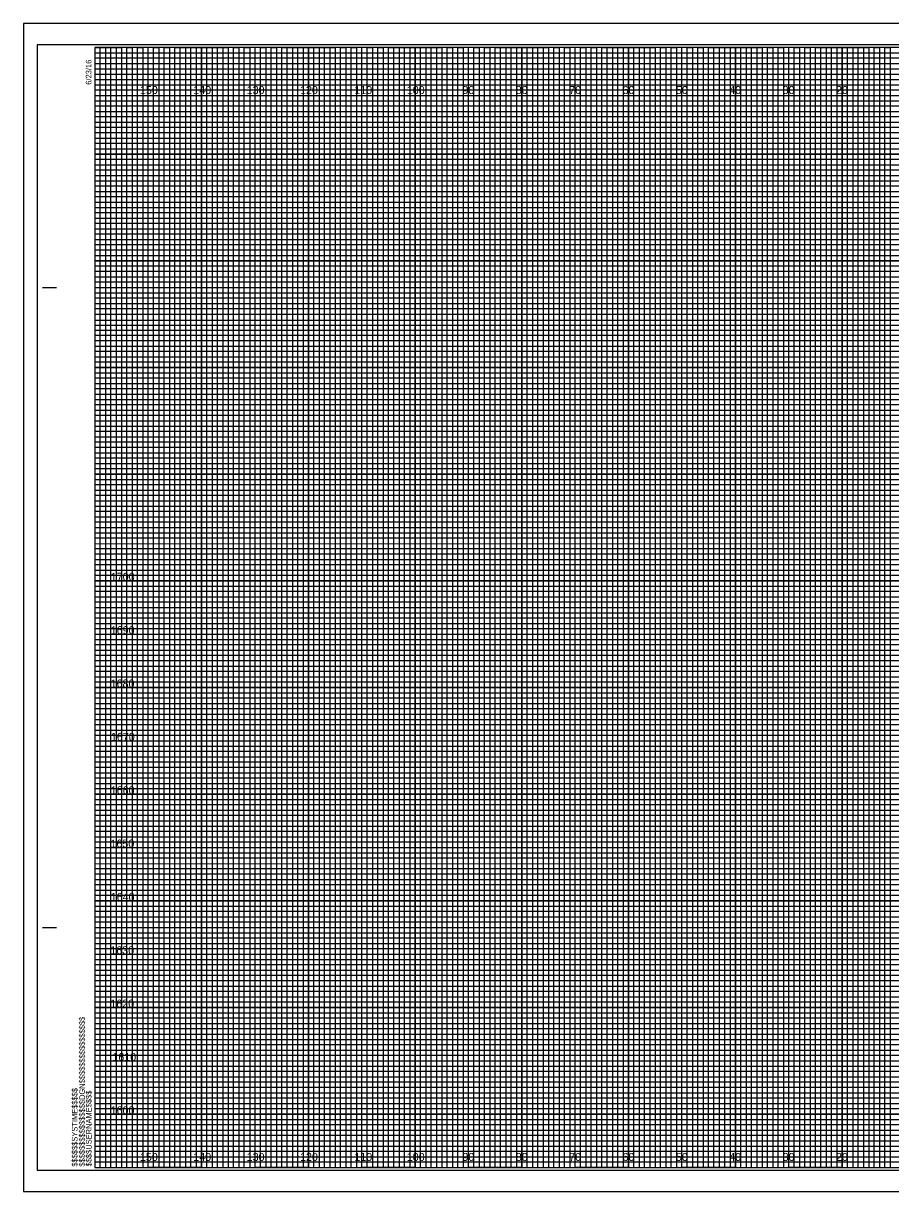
# Model space of a CAD drawing. Extents: x -13 to 323, y -5 to 6154.
# Drawn here: x -13.4 to 149.1, y 5275.5 to 5494.5 of the extents above; entities that cross this region are included whole.
import ezdxf

# ---------------------------------------------------------------- set-up
doc = ezdxf.new("R2010")
doc.units = 0
for name, color, linetype in [('Prop Retaining Wall', 7, 'Continuous'), ('Prop XS Alignment Label', 7, 'Continuous'), ('Prop XS DDE', 7, 'Continuous'), ('Prop XS DDE Elevations', 7, 'Continuous'), ('Prop XS DDE Slope Text', 7, 'Continuous'), ('Prop XS Earthwork Shape', 7, 'Continuous'), ('Prop XS Elevation Labels', 7, 'Continuous'), ('Prop XS Station Labels', 7, 'Continuous'), ('Raster_Level_0', 7, 'Continuous'), ('Scratch_Level_3', 7, 'Continuous'), ('Sheet Cutting Line CELL', 7, 'Continuous')]:
    doc.layers.add(name, color=color, linetype=linetype)

msp = doc.modelspace()

# ---------------------------------------------------------------- linework, layer by layer
at = {"layer": 'Prop Retaining Wall'}
for p, q in [((0, 5489), (260, 5489)), ((260, 5487.98), (0, 5487.98)), ((0, 5487.98), (0, 5487)), ((0, 5487), (260, 5487)), ((260, 5485.89), (0, 5485.89)), ((0, 5485.89), (0, 5484)), ((0, 5484), (320, 5484))]:
    msp.add_line(p, q, dxfattribs=at)
for points in [[(0, 5483), (270, 5483), (320, 5483), (320, 5482), (0, 5482)], [(0, 5481), (320, 5481), (320, 5479), (0, 5479)], [(0, 5478), (320, 5478), (320, 5477), (0, 5476.98)], [(0, 5476), (320, 5476), (320, 5474), (0, 5474)], [(0, 5473), (320, 5473), (320, 5472), (0, 5472)], [(0, 5471), (320, 5471), (320, 5469), (0, 5469)], [(0, 5468), (320, 5468), (320, 5467), (0, 5467)], [(0, 5466), (320, 5466), (320, 5464), (0, 5464)], [(0, 5463), (320, 5463), (320, 5462), (0, 5462)], [(0, 5461), (320, 5461), (320, 5459), (0, 5459)], [(0, 5458), (320, 5458), (320, 5457), (0, 5457)], [(0, 5456), (320, 5456), (320, 5453.95), (320, 5453), (320, 5452), (0, 5452)], [(0, 5454), (320, 5454), (320, 5453), (0, 5453)], [(0, 5451), (320, 5451), (320, 5449), (0, 5449.03)], [(0, 5449.03), (320, 5449), (320, 5448), (0, 5448)], [(0, 5447), (320, 5447), (320, 5446), (0, 5446)], [(0, 5444), (320, 5444), (320, 5443), (0, 5443)], [(0, 5442), (320, 5442), (320, 5441), (0, 5441)], [(-0.07, 5438.89), (320, 5438.89), (320, 5437.88), (-0.07, 5437.88)], [(0, 5437), (320, 5437), (320, 5436), (0, 5436)], [(0, 5434), (320, 5434), (320, 5433), (0, 5433)], [(0, 5432), (320, 5432), (320, 5431), (0, 5431)], [(0, 5429), (320, 5429), (320, 5428), (0, 5428)], [(0, 5427), (320, 5427), (320, 5426), (0, 5426)], [(0, 5424), (320, 5424), (320, 5423), (0, 5423)], [(0, 5422), (320, 5422), (320, 5421), (0, 5421)], [(0, 5419), (320, 5419), (319.99, 5417.98), (0, 5418)], [(0, 5417), (320, 5417), (320, 5416), (0, 5416)], [(0, 5414), (320, 5414), (320, 5413), (0, 5413)], [(0, 5412), (320, 5412), (320, 5411), (0, 5411)], [(0, 5409), (320, 5409), (320, 5408), (0, 5408)], [(0, 5407), (320, 5407), (320, 5406), (0, 5406)], [(0, 5404), (320, 5404), (320, 5403), (0, 5403)], [(0, 5402), (320, 5402), (320, 5401), (0, 5401)], [(0, 5399), (320, 5399), (320, 5398), (0, 5398)], [(0, 5396.99), (320.07, 5396.91), (320, 5396), (0, 5396)], [(0, 5394), (320, 5394), (320, 5393), (0, 5393)], [(0, 5392), (320, 5392), (320, 5391), (0, 5391)], [(0, 5389), (320, 5389), (320, 5388), (0, 5388)], [(0, 5387), (320, 5387), (320, 5386), (0, 5386)], [(0, 5384), (320, 5384), (320, 5383), (0, 5383)], [(0, 5382), (320, 5382), (320, 5381), (0, 5381)], [(0, 5379), (320, 5379), (320, 5378), (0, 5378)], [(0, 5377), (320, 5377), (320, 5376), (0, 5376)], [(0, 5374), (320, 5374), (320, 5373), (0, 5373)], [(0, 5372), (320, 5372), (320, 5371), (0, 5371)], [(0, 5369), (320, 5369), (320, 5368), (0, 5368)], [(0, 5367), (320, 5367), (320, 5366), (0, 5366)], [(0, 5364), (320, 5364), (320, 5363), (0, 5363)], [(0, 5362), (320, 5362), (320, 5361), (0, 5361)], [(0, 5359), (320, 5359), (319.99, 5357.98), (0, 5358)], [(0, 5357), (320, 5357), (320, 5356), (0, 5356)], [(0, 5354), (320, 5354), (320, 5353), (0, 5353)], [(0, 5352), (320, 5352), (320, 5351), (0, 5351)], [(0, 5349), (320, 5349), (320, 5348), (0, 5348)], [(0, 5347), (320, 5347), (320, 5346), (0, 5346)], [(0, 5344), (320, 5344), (320, 5343), (0, 5343)], [(0, 5342), (320, 5342), (320, 5341), (0, 5341)], [(0, 5339), (320, 5339), (320, 5338), (0, 5338)], [(0, 5336.99), (320.07, 5336.91), (320, 5336), (0, 5336)], [(0, 5334), (320, 5334), (320, 5333), (0, 5333)], [(0, 5332), (320, 5332), (320, 5331), (0, 5331)], [(0, 5329), (320, 5329), (320, 5328), (0, 5328)], [(0, 5327), (320, 5327), (320, 5326), (0, 5326)], [(0, 5324), (320, 5324), (320, 5323), (0, 5323)], [(0, 5322), (320, 5322), (320, 5321), (0, 5321)], [(0, 5319), (320, 5319), (320, 5318), (0, 5318)], [(0, 5317), (320, 5317), (320, 5316), (0, 5316)], [(0, 5314), (320, 5314), (320, 5313), (0, 5313)], [(0, 5312), (320, 5312), (320, 5311), (0, 5311)], [(0, 5309), (320, 5309), (320, 5308), (0, 5308)], [(0, 5307), (320, 5307), (320, 5306), (0, 5306)], [(0, 5304), (320, 5304), (320, 5303), (0, 5303)], [(0, 5302), (320, 5302), (320, 5301), (0, 5301)], [(0, 5299), (320, 5299), (320, 5298), (0, 5298)], [(0, 5297), (320, 5297), (320, 5296), (0, 5296)], [(0, 5294), (320, 5294), (320, 5293), (0, 5293)], [(0, 5292), (320, 5292), (320, 5291), (0, 5291)], [(0, 5289), (320, 5289), (320, 5288), (0, 5288)], [(0, 5287), (320, 5287), (320, 5286), (0, 5286)], [(0, 5284), (320, 5284), (320, 5283), (0, 5283)], [(0, 5282), (320, 5282), (320, 5281), (0, 5281)]]:
    msp.add_lwpolyline(points, dxfattribs=at)
at = {"layer": 'Prop XS Alignment Label'}
for p, q in [((-9.8, 5445), (-7.3, 5445)), ((-9.7, 5445), (-7.2, 5445)), ((-9.8, 5325), (-7.3, 5325)), ((-9.7, 5325), (-7.2, 5325)), ((0, 5280), (0, 5280)), ((0, 5280), (0, 5280)), ((0, 5280), (0, 5280)), ((0, 5280), (0, 5280)), ((0, 5280), (0, 5280)), ((0, 5280), (0, 5280)), ((0, 5280), (0, 5280))]:
    msp.add_line(p, q, dxfattribs=at)
msp.add_lwpolyline([(320, 5490), (0, 5490), (0, 5280), (320, 5280)], close=True, dxfattribs=at)
at = {"layer": 'Prop XS DDE'}
msp.add_lwpolyline([(-13.4, 5275.5), (323.3, 5275.5), (323.3, 5494.5), (-13.4, 5494.5)], close=True, dxfattribs=at)
at = {"layer": 'Prop XS DDE Elevations'}
for p, q in [((10, 5280), (10, 5490)), ((20, 5280), (20, 5490)), ((30, 5280), (30, 5490)), ((40, 5280), (40, 5490)), ((50, 5280), (50, 5490)), ((60, 5280), (60, 5490)), ((70, 5280), (70, 5490)), ((80, 5280), (80, 5490)), ((90, 5280), (90, 5490)), ((100, 5280), (100, 5490)), ((110, 5280), (110, 5490)), ((120, 5280), (120, 5490)), ((130, 5280), (130, 5490)), ((140, 5280), (140, 5490)), ((0, 5480), (320, 5480)), ((0, 5470), (320, 5470)), ((0, 5460), (320, 5460)), ((0, 5450), (320, 5450)), ((0, 5440), (320, 5440)), ((0, 5430), (320, 5430)), ((0, 5420), (320, 5420)), ((0, 5410), (320, 5410)), ((0, 5400), (320, 5400)), ((0, 5390), (320, 5390)), ((0, 5380), (320, 5380)), ((0, 5370), (320, 5370)), ((0, 5360), (320, 5360)), ((0, 5350), (320, 5350)), ((0, 5340), (320, 5340)), ((0, 5330), (320, 5330)), ((0, 5320), (320, 5320)), ((0, 5310), (320, 5310)), ((0, 5300), (320, 5300)), ((0, 5290), (320, 5290))]:
    msp.add_line(p, q, dxfattribs=at)
at = {"layer": 'Prop XS DDE Slope Text'}
msp.add_lwpolyline([(-10.8, 5279.5), (322.4, 5279.5), (322.4, 5490.5), (-10.8, 5490.5)], close=True, dxfattribs=at)
at = {"layer": 'Prop XS Earthwork Shape'}
for p, q in [((10, 5490), (0, 5490)), ((10, 5280), (10, 5490)), ((30, 5490), (20, 5490)), ((20, 5490), (20, 5280)), ((30, 5280), (30, 5490)), ((50, 5490), (40, 5490)), ((40, 5490), (40, 5280)), ((50, 5280), (50, 5490)), ((70, 5490), (60, 5490)), ((60, 5490), (60, 5280)), ((70, 5280), (70, 5490)), ((90, 5490), (80, 5490)), ((80, 5490), (80, 5280)), ((90, 5280), (90, 5490)), ((110, 5490), (100, 5490)), ((100, 5490), (100, 5280)), ((110, 5280), (110, 5490)), ((130, 5490), (120, 5490)), ((120, 5490), (120, 5280)), ((130, 5280), (130, 5490)), ((150, 5490), (140, 5490)), ((140, 5490), (140, 5280)), ((20, 5280), (10, 5280)), ((40, 5280), (30, 5280)), ((60, 5280), (50, 5280)), ((80, 5280), (70, 5280)), ((100, 5280), (90, 5280)), ((120, 5280), (110, 5280)), ((140, 5280), (130, 5280))]:
    msp.add_line(p, q, dxfattribs=at)
for points in [[(0, 5480), (320, 5480), (320, 5470), (0, 5470)], [(0, 5460), (320, 5460), (320, 5450), (0, 5450)], [(0, 5440), (320, 5440), (320, 5430), (0, 5430)], [(0, 5420), (320, 5420), (320, 5410), (0, 5410)], [(0, 5400), (320, 5400), (320, 5390), (0, 5390)], [(0, 5380), (320, 5380), (320, 5370), (0, 5370)], [(0, 5360), (320, 5360), (320, 5350), (0, 5350)], [(0, 5340), (320, 5340), (320, 5330), (0, 5330)], [(0, 5320), (320, 5320), (320, 5310), (0, 5310)], [(0, 5300), (320, 5300), (320, 5290), (0, 5290)]]:
    msp.add_lwpolyline(points, dxfattribs=at)
at = {"layer": 'Prop XS Elevation Labels'}
for points in [[(0, 5280), (1, 5280), (1, 5490), (2, 5490), (2, 5280)], [(2, 5280), (3, 5280), (3, 5490), (4, 5490), (4, 5280)], [(5, 5280), (6, 5280), (6, 5490), (7, 5490), (7, 5280)], [(7, 5280), (8, 5280), (8, 5490), (9, 5490), (9, 5280)], [(10, 5280), (11, 5280), (11, 5490), (12, 5490), (12, 5280)], [(12, 5280), (13, 5280), (13, 5490), (14, 5490), (14, 5280)], [(15, 5280), (16, 5280), (16, 5490), (17, 5490), (17, 5280)], [(17, 5280), (18, 5280), (18, 5490), (19, 5490), (19, 5280)], [(20, 5280), (21, 5280), (21, 5490), (22, 5490), (22, 5280)], [(22, 5280), (23, 5280), (23, 5490), (24, 5490), (24, 5280)], [(25, 5280), (26, 5280), (26, 5490), (27, 5490), (27, 5280)], [(27, 5280), (28, 5280), (28, 5490), (29, 5490), (29, 5280)], [(30, 5280), (31, 5280), (31, 5490), (32, 5490), (32, 5280)], [(32, 5280), (33, 5280), (33, 5490), (34, 5490), (34, 5280)], [(35, 5280), (36, 5280), (36, 5490), (37, 5490), (37, 5280)], [(37, 5280), (38, 5280), (38, 5490), (39, 5490), (39, 5280)], [(40, 5280), (41, 5280), (41, 5490), (42, 5490), (42, 5280)], [(42, 5280), (43, 5280), (43, 5490), (44, 5490), (44, 5280)], [(45, 5280), (46, 5280), (46, 5490), (47, 5490), (47, 5280)], [(47, 5280), (48, 5280), (48, 5490), (49, 5490), (49, 5280)], [(50, 5280), (51, 5280), (51, 5490), (52, 5490), (52, 5280)], [(52, 5280), (53, 5280), (53, 5490), (54, 5490), (54, 5280)], [(55, 5280), (56, 5280), (56, 5490), (57, 5490), (57, 5280)], [(57, 5280), (58, 5280), (58, 5490), (59, 5490), (59, 5280)], [(60, 5280), (61, 5280), (61, 5490), (62, 5490), (62, 5280)], [(62, 5280), (63, 5280), (63, 5490), (64, 5490), (64, 5280)], [(65, 5280), (66, 5280), (66, 5490), (67, 5490), (67, 5280)], [(67, 5280), (68, 5280), (68, 5490), (69, 5490), (69, 5280)], [(70, 5280), (71, 5280), (71, 5490), (72, 5490), (72, 5280)], [(72, 5280), (73, 5280), (73, 5490), (74, 5490), (74, 5280)], [(75, 5280), (76, 5280), (76, 5490), (77, 5490), (77, 5280)], [(77, 5280), (78, 5280), (78, 5490), (79, 5490), (79, 5280)], [(80, 5280), (81, 5280), (81, 5490), (82, 5490), (82, 5280)], [(82, 5280), (83, 5280), (83, 5490), (84, 5490), (84, 5280)], [(85, 5280), (86, 5280), (86, 5490), (87, 5490), (87, 5280)], [(87, 5280), (88, 5280), (88, 5490), (89, 5490), (89, 5280)], [(90, 5280), (91, 5280), (91, 5490), (92, 5490), (92, 5280)], [(92, 5280), (93, 5280), (93, 5490), (94, 5490), (94, 5280)], [(95, 5280), (96, 5280), (96, 5490), (97, 5490), (97, 5280)], [(97, 5280), (98, 5280), (98, 5490), (99, 5490), (99, 5280)], [(100, 5280), (101, 5280), (101, 5490), (102, 5490), (102, 5280)], [(102, 5280), (103, 5280), (103, 5490), (104, 5490), (104, 5280)], [(105, 5280), (106, 5280), (106, 5490), (107, 5490), (107, 5280)], [(107, 5280), (108, 5280), (108, 5490), (109, 5490), (109, 5280)], [(110, 5280), (111, 5280), (111, 5490), (112, 5490), (112, 5280)], [(112, 5280), (113, 5280), (113, 5490), (114, 5490), (114, 5280)], [(115, 5280), (116, 5280), (116, 5490), (117, 5490), (117, 5280)], [(117, 5280), (118, 5280), (118, 5490), (119, 5490), (119, 5280)], [(120, 5280), (121, 5280), (121, 5490), (122, 5490), (122, 5280)], [(122, 5280), (123, 5280), (123, 5490), (124, 5490), (124, 5280)], [(125, 5280), (126, 5280), (126, 5490), (127, 5490), (127, 5280)], [(127, 5280), (128, 5280), (128, 5490), (129, 5490), (129, 5280)], [(130, 5280), (131, 5280), (131, 5490), (132, 5490), (132, 5280)], [(132, 5280), (133, 5280), (133, 5490), (134, 5490), (134, 5280)], [(135, 5280), (136, 5280), (136, 5490), (137, 5490), (137, 5280)], [(137, 5280), (138, 5280), (138, 5490), (139, 5490), (139, 5280)], [(140, 5280), (141, 5280), (141, 5490), (142, 5490), (142, 5280)], [(142, 5280), (143, 5280), (143, 5490), (144, 5490), (144, 5280)], [(145, 5280), (146, 5280), (146, 5490), (147, 5490), (147, 5280)], [(147, 5280), (148, 5280), (148, 5490), (149, 5490), (149, 5280)]]:
    msp.add_lwpolyline(points, dxfattribs=at)
at = {"layer": 'Prop XS Station Labels'}
for points in [[(0, 5490), (5, 5490), (5, 5280), (15, 5280), (15, 5490), (25, 5490), (25, 5280), (35, 5280), (35, 5490), (45, 5490), (45, 5280), (55, 5280), (55, 5490), (65, 5490), (65, 5280), (75, 5280), (75, 5490), (85, 5490), (85, 5280), (95, 5280), (95, 5490), (105, 5490), (105, 5280), (115, 5280), (115, 5490), (125, 5490), (125, 5280), (135, 5280), (135, 5490), (145, 5490), (145, 5280), (155, 5280)], [(0, 5485), (275, 5485)], [(0, 5465), (320, 5465), (320, 5475), (0, 5475)], [(0, 5445), (320, 5445), (320, 5455), (0, 5455)], [(0, 5425), (320, 5425), (320, 5435), (0, 5435)], [(0, 5405), (320, 5405), (320, 5415), (0, 5415)], [(0, 5385), (320, 5385), (320, 5395), (0, 5395)], [(0, 5365), (320, 5365), (320, 5375), (0, 5375)], [(0, 5345), (320, 5345), (320, 5355), (0, 5355)], [(0, 5325), (320, 5325), (320, 5335), (0, 5335)], [(0, 5305), (320, 5305), (320, 5315), (0, 5315)], [(0, 5285), (320, 5285), (320, 5295), (0, 5295)]]:
    msp.add_lwpolyline(points, dxfattribs=at)
at = {"layer": 'Sheet Cutting Line CELL'}
for p, q in [((323.3, 5494.5), (-13.4, 5494.5)), ((-13.4, 5494.5), (-13.4, 5275.5)), ((-13.4, 5275.5), (323.3, 5275.5))]:
    msp.add_line(p, q, dxfattribs=at)

# ---------------------------------------------------------------- texts
at = {"layer": 'Prop XS Alignment Label'}
for s, p in [('6/23/16', (-0.65, 5483)), ('$$$$$$$$$$$$$$$$DGN$$$$$$$$$$$$$$$$', (-1.88, 5280.18)), ('$$$$$$SYSTIME$$$$$', (-3.26, 5280.18)), ('$$$$USERNAME$$$$', (-0.62, 5280.23))]:
    msp.add_text(s, height=1.05, rotation=90, dxfattribs=at).set_placement(p)
at = {"layer": 'Raster_Level_0'}
for s, p in [('150', (8.44, 5481.25)), ('140', (18.44, 5481.25)), ('130', (28.44, 5481.25)), ('120', (38.44, 5481.25)), ('110', (48.62, 5481.25)), ('100', (58.44, 5481.25)), ('90', (68.86, 5481.25)), ('80', (78.86, 5481.25)), ('70', (88.86, 5481.25)), ('60', (98.86, 5481.25)), ('50', (108.86, 5481.25)), ('40', (118.86, 5481.25)), ('30', (128.86, 5481.25)), ('20', (138.86, 5481.25)), ('150', (8.44, 5281.25)), ('140', (18.44, 5281.25)), ('130', (28.44, 5281.25)), ('120', (38.44, 5281.25)), ('110', (48.62, 5281.25)), ('100', (58.44, 5281.25)), ('90', (68.86, 5281.25)), ('80', (78.86, 5281.25)), ('70', (88.86, 5281.25)), ('60', (98.86, 5281.25)), ('50', (108.86, 5281.25)), ('40', (118.86, 5281.25)), ('30', (128.86, 5281.25)), ('20', (138.86, 5281.25))]:
    msp.add_text(s, height=1.5, dxfattribs=at).set_placement(p)
at = {"layer": 'Scratch_Level_3'}
for s, p in [('1700', (2.98, 5390)), ('1690', (2.97, 5380)), ('1680', (2.95, 5370)), ('1670', (3, 5360)), ('1660', (2.97, 5350)), ('1650', (2.92, 5340)), ('1640', (2.97, 5330)), ('1630', (2.89, 5320)), ('1620', (2.9, 5310)), ('1610', (3.28, 5300)), ('1600', (2.95, 5290))]:
    msp.add_text(s, height=1.5, dxfattribs=at).set_placement(p)

doc.saveas('drawing.dxf')
